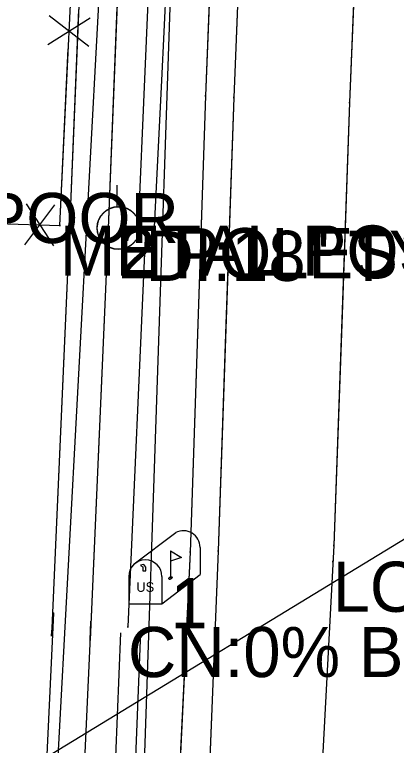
# Model space of a CAD drawing. Extents: x -99999 to 591807, y -99999 to 347168.
# Drawn here: x 591214 to 591252.1, y 320523.7 to 320596.6 of the extents above; entities that cross this region are included whole.
import ezdxf

# ---------------------------------------------------------------- set-up
doc = ezdxf.new("R2010")
doc.units = 0
for name, color, linetype in [('S_CURB', 7, 'Continuous'), ('S_DITCHLINE', 7, 'Continuous'), ('S_DRG_PT_SYM', 7, 'Continuous'), ('S_EDGE_PAVEMENT', 7, 'Continuous'), ('S_ELECTRIC_UTILITIES_ANNOT', 7, 'Continuous'), ('S_FENCE', 7, 'Continuous'), ('S_FENCE_ANNOT', 7, 'Continuous'), ('S_GAS_UTILITIES', 7, 'Continuous'), ('S_GRD_PT_SYM', 7, 'Continuous'), ('S_MAILBOX', 7, 'Continuous'), ('S_MAILBOX_ANNOT', 7, 'Continuous'), ('S_MSC_PT_SYM', 7, 'Continuous'), ('S_PAVEMENT_CROWN', 7, 'Continuous'), ('S_RDW_PT_SYM', 7, 'Continuous'), ('S_SHOULDER', 7, 'Continuous'), ('S_SIDE_DRAIN', 7, 'Continuous'), ('S_SIDE_DRAIN_ANNOT', 7, 'Continuous'), ('S_SIDEWALK', 7, 'Continuous'), ('S_UTILITY_POLE', 7, 'Continuous'), ('S_UTILITY_POLE_ANNOT', 7, 'Continuous'), ('S_UTL_PT_SYM', 7, 'Continuous'), ('S_WATER_UTILITIES', 7, 'Continuous')]:
    doc.layers.add(name, color=color, linetype=linetype)

msp = doc.modelspace()

# ---------------------------------------------------------------- linework, layer by layer
at = {"layer": 'S_CURB'}
msp.add_lwpolyline([(591407.501, 320558.912), (591363.862, 320560.823), (591322.937, 320562.802), (591286.066, 320564.459), (-99999, -99999)], dxfattribs=at)
at = {"layer": 'S_DITCHLINE'}
for points in [[(591226.335, 320575.526), (591226.979, 320590.136), (591227.623, 320604.745), (591228.267, 320619.355), (591228.911, 320633.965)], [(591227.95, 320575.425), (591228.667, 320589.998), (591229.385, 320604.572), (591230.103, 320619.146), (591230.821, 320633.72)], [(591223.986, 320468.51), (591224.633, 320485.141), (591225.28, 320501.773), (591225.927, 320518.405), (591226.574, 320535.036)], [(591222.009, 320468.936), (591222.651, 320485.44), (591223.293, 320501.945), (591223.935, 320518.45), (591224.577, 320534.954)]]:
    msp.add_lwpolyline(points, dxfattribs=at)
at = {"layer": 'S_DRG_PT_SYM'}
for points in [[(591227.047, 320575.022), (591227.047, 320575.072), (591227.047, 320575.022), (591226.997, 320575.022), (591227.047, 320575.022), (591227.047, 320574.972), (591227.047, 320575.022), (591227.097, 320575.022)], [(591225.295, 320535.531), (591225.295, 320535.582), (591225.295, 320535.531), (591225.245, 320535.531), (591225.295, 320535.531), (591225.295, 320535.481), (591225.295, 320535.531), (591225.345, 320535.531)]]:
    msp.add_lwpolyline(points, dxfattribs=at)
at = {"layer": 'S_EDGE_PAVEMENT'}
for points in [[(591157.816, 321374.558), (591171.996, 321326.2), (591184.501, 321283.667), (591196.965, 321241.411), (591212.283, 321187.826), (591223.284, 321148.219), (591233.116, 321106.873), (591242.974, 321050.292), (591247.278, 321006.148), (591248.487, 320958.254), (591248.173, 320914.304), (591247.117, 320868.716), (591245.559, 320824.189), (591244.165, 320785.581), (591242.251, 320742.557), (591240.726, 320705.613), (591238.924, 320663.696), (591237.267, 320623.329), (591235.848, 320588.307), (591234.304, 320543.116), (591232.694, 320503.413), (591231.224, 320460.428), (591229.562, 320424.545)], [(591236.557, 320605.818), (591235.848, 320588.307), (591235.076, 320565.712), (591234.304, 320543.116), (591233.499, 320523.265), (591232.694, 320503.413), (591231.959, 320481.921), (591231.224, 320460.428), (591230.393, 320442.487), (591229.562, 320424.545)]]:
    msp.add_lwpolyline(points, dxfattribs=at)
at = {"layer": 'S_FENCE'}
for p, q in [((591218.492, 320575.546), (591221.353, 320634.933)), ((591217.311, 320593.587), (591221.54, 320596.255)), ((591221.402, 320593.39), (591217.449, 320596.452)), ((591124.877, 320578.793), (591218.492, 320575.546)), ((591214.998, 320573.618), (591218.006, 320577.612)), ((591215.14, 320577.712), (591217.864, 320573.519))]:
    msp.add_line(p, q, dxfattribs=at)
msp.add_lwpolyline([(591218.492, 320575.546), (591219.341, 320593.16)], dxfattribs=at)
at = {"layer": 'S_GAS_UTILITIES'}
msp.add_line((591229.99, 320612.067), (591224.377, 320448.24), dxfattribs=at)
at = {"layer": 'S_GRD_PT_SYM'}
msp.add_lwpolyline([(591245.733, 320542.039), (591245.733, 320542.089), (591245.733, 320542.039), (591245.682, 320542.039), (591245.733, 320542.039), (591245.733, 320541.989), (591245.733, 320542.039), (591245.783, 320542.039)], close=True, dxfattribs=at)
at = {"layer": 'S_MAILBOX'}
for p, q in [((591225.926, 320541.824), (591230.06, 320544.933)), ((591229.541, 320543.113), (591229.541, 320540.398)), ((591232.492, 320543.459), (591232.492, 320540.744)), ((591225.372, 320540.55), (591225.372, 320537.835)), ((591228.696, 320537.835), (591232.492, 320540.744)), ((591228.696, 320540.55), (591228.696, 320537.835)), ((591225.372, 320537.835), (591228.696, 320537.835))]:
    msp.add_line(p, q, dxfattribs=at)
for points in [[(591229.541, 320543.113), (591230.649, 320542.448), (591229.541, 320542.102)], [(591226.556, 320541.665), (591226.778, 320541.527), (591226.778, 320541.139), (591227.083, 320541.139), (591227.083, 320541.499), (591226.889, 320541.748), (591226.556, 320541.693)]]:
    msp.add_lwpolyline(points, dxfattribs=at)
for centre, end in [((591230.83, 320543.459), 117.57184), ((591227.034, 320540.55), 180)]:
    msp.add_arc(centre, 1.662, 0, end, dxfattribs=at)
msp.add_ellipse((591229.541, 320540.398), major_axis=(0.145, 0.132), ratio=0.564646, dxfattribs=at)
at = {"layer": 'S_MSC_PT_SYM'}
for points in [[(591219.52, 320576.847), (591219.57, 320576.845), (591219.52, 320576.847), (591219.522, 320576.897), (591219.52, 320576.847), (591219.47, 320576.85), (591219.52, 320576.847), (591219.517, 320576.797)], [(591223.33, 320575.279), (591223.38, 320575.277), (591223.33, 320575.279), (591223.332, 320575.329), (591223.33, 320575.279), (591223.28, 320575.281), (591223.33, 320575.279), (591223.328, 320575.229)], [(591217.863, 320536.898), (591217.913, 320536.895), (591217.863, 320536.898), (591217.866, 320536.948), (591217.863, 320536.898), (591217.814, 320536.9), (591217.863, 320536.898), (591217.861, 320536.848)], [(591221.586, 320536.045), (591221.636, 320536.042), (591221.586, 320536.045), (591221.588, 320536.094), (591221.586, 320536.045), (591221.536, 320536.047), (591221.586, 320536.045), (591221.584, 320535.995)], [(591217.679, 320534.666), (591217.629, 320534.671), (591217.679, 320534.666), (591217.674, 320534.617), (591217.679, 320534.666), (591217.728, 320534.662), (591217.679, 320534.666), (591217.683, 320534.716)], [(591221.529, 320534.239), (591221.479, 320534.241), (591221.529, 320534.239), (591221.527, 320534.189), (591221.529, 320534.239), (591221.579, 320534.238), (591221.529, 320534.239), (591221.53, 320534.289)]]:
    msp.add_lwpolyline(points, close=True, dxfattribs=at)
msp.add_lwpolyline([(591218.492, 320575.546), (591218.492, 320575.596), (591218.492, 320575.546), (591218.442, 320575.546), (591218.492, 320575.546), (591218.492, 320575.496), (591218.492, 320575.546), (591218.542, 320575.546)], dxfattribs=at)
at = {"layer": 'S_PAVEMENT_CROWN'}
for points in [[(591169.393, 321376.166), (591182.702, 321330.303), (591196.053, 321285.507), (591208.234, 321244.204), (591224.138, 321189.501), (591234.43, 321151.835), (591245.74, 321106.049), (591255.457, 321050.575), (591259.103, 321006.376), (591260.258, 320958.142), (591259.827, 320913.406), (591258.406, 320868.937), (591257.042, 320823.073), (591255.423, 320785.261), (591253.776, 320741.805), (591252.116, 320704.89), (591250.293, 320661.391), (591248.847, 320623.224), (591247.409, 320587.797), (591245.838, 320543.645), (591243.645, 320502.375), (591242.309, 320460.161), (591240.802, 320424.401)], [(591248.128, 320605.51), (591247.409, 320587.797), (591246.623, 320565.721), (591245.838, 320543.645), (591244.741, 320523.01), (591243.645, 320502.375), (591242.977, 320481.268), (591242.309, 320460.161), (591241.556, 320442.281), (591240.802, 320424.401)]]:
    msp.add_lwpolyline(points, dxfattribs=at)
at = {"layer": 'S_RDW_PT_SYM'}
for points in [[(591233.024, 320588.472), (591233.074, 320588.471), (591233.024, 320588.472), (591233.025, 320588.522), (591233.024, 320588.472), (591232.974, 320588.474), (591233.024, 320588.472), (591233.022, 320588.422)], [(591235.848, 320588.307), (591235.898, 320588.305), (591235.848, 320588.307), (591235.85, 320588.357), (591235.848, 320588.307), (591235.798, 320588.309), (591235.848, 320588.307), (591235.846, 320588.257)], [(591247.409, 320587.797), (591247.459, 320587.795), (591247.409, 320587.797), (591247.41, 320587.847), (591247.409, 320587.797), (591247.359, 320587.799), (591247.409, 320587.797), (591247.407, 320587.747)], [(591234.304, 320543.116), (591234.354, 320543.114), (591234.304, 320543.116), (591234.306, 320543.166), (591234.304, 320543.116), (591234.254, 320543.118), (591234.304, 320543.116), (591234.302, 320543.066)], [(591245.838, 320543.645), (591245.887, 320543.642), (591245.838, 320543.645), (591245.84, 320543.695), (591245.838, 320543.645), (591245.788, 320543.648), (591245.838, 320543.645), (591245.835, 320543.595)], [(591231.51, 320542.985), (591231.559, 320542.983), (591231.51, 320542.985), (591231.512, 320543.035), (591231.51, 320542.985), (591231.46, 320542.987), (591231.51, 320542.985), (591231.507, 320542.935)]]:
    msp.add_lwpolyline(points, close=True, dxfattribs=at)
at = {"layer": 'S_SHOULDER'}
for points in [[(591245.875, 320932.116), (591246.336, 320914.379), (591244.03, 320869.095), (591242.236, 320824.086), (591240.926, 320786.072), (591238.956, 320744.968), (591237.561, 320705.47), (591236.035, 320663.813), (591234.455, 320624.274), (591233.024, 320588.472), (591231.51, 320542.985), (591229.6, 320503.548), (591227.673, 320460.661), (591225.848, 320425.042)], [(591233.739, 320606.373), (591233.024, 320588.472), (591232.267, 320565.729), (591231.51, 320542.985), (591230.555, 320523.267), (591229.6, 320503.548), (591228.637, 320482.105), (591227.673, 320460.661), (591226.761, 320442.852), (591225.848, 320425.042)]]:
    msp.add_lwpolyline(points, dxfattribs=at)
at = {"layer": 'S_SIDE_DRAIN'}
msp.add_line((591227.047, 320575.022), (591225.295, 320535.531), dxfattribs=at)
at = {"layer": 'S_SIDEWALK'}
for points in [[(591219.908, 320876.067), (591231.73, 320875.493), (591230.676, 320851.856), (591229.672, 320820.621), (591229.014, 320806.939), (591228.338, 320790.518), (591228.051, 320787.963), (591226.647, 320756.32), (591225.614, 320729.855), (591224.094, 320691.665), (591222.325, 320649.311), (591221.216, 320617.3), (591219.52, 320576.847), (591217.679, 320534.666), (591217.863, 320536.898), (591216.224, 320501.633), (591214.624, 320467.913), (591200.757, 320468.742)], [(591225.013, 320617.584), (591223.33, 320575.279), (591221.529, 320534.239), (591221.586, 320536.045), (591219.997, 320501.136), (591218.495, 320468.181), (591225.523, 320467.907), (591225.412, 320464.068), (591218.297, 320464.183), (591216.954, 320432.825)], [(591225.013, 320617.584), (591224.171, 320596.432), (591223.33, 320575.279), (591222.429, 320554.759), (591221.529, 320534.239), (591221.586, 320536.045), (591220.791, 320518.59), (591219.997, 320501.136), (591219.246, 320484.658), (591218.495, 320468.181), (591225.523, 320467.907), (591225.412, 320464.068), (591218.297, 320464.183), (591217.625, 320448.504), (591216.954, 320432.825)], [(591220.368, 320597.074), (591219.52, 320576.847), (591218.599, 320555.757), (591217.679, 320534.666), (591217.863, 320536.898), (591217.044, 320519.265), (591216.224, 320501.633), (591215.424, 320484.773), (591214.624, 320467.913), (591200.757, 320468.742)]]:
    msp.add_lwpolyline(points, dxfattribs=at)
at = {"layer": 'S_UTILITY_POLE'}
for p, q in [((591224.239, 320577.451), (591224.239, 320579.559)), ((591224.239, 320577.425), (591224.239, 320579.533))]:
    msp.add_line(p, q, dxfattribs=at)
for centre in [(591224.361, 320575.309), (591224.362, 320575.284)]:
    msp.add_circle(centre, 2.127, dxfattribs=at)
at = {"layer": 'S_UTL_PT_SYM'}
msp.add_lwpolyline([(591245.733, 320542.039), (591245.733, 320542.089), (591245.733, 320542.039), (591245.682, 320542.039), (591245.733, 320542.039), (591245.733, 320541.989), (591245.733, 320542.039), (591245.783, 320542.039)], dxfattribs=at)
at = {"layer": 'S_WATER_UTILITIES'}
msp.add_line((591223.46, 320618.063), (591214.304, 320448.446), dxfattribs=at)

# ---------------------------------------------------------------- texts
at = {"layer": 'S_ELECTRIC_UTILITIES_ANNOT'}
msp.add_text('LOWEST UTILITY LINE', height=5, dxfattribs=at).set_placement((591245.733, 320537.039))
at = {"layer": 'S_FENCE_ANNOT'}
for p in [(591124.877, 320573.793), (591218.492, 320570.546)]:
    msp.add_text('METAL POST WEBED NET,POOR', height=5, dxfattribs=at).set_placement(p)
at = {"layer": 'S_MAILBOX'}
msp.add_text('US', height=0.96, rotation=360, dxfattribs=at).set_placement((591226.136, 320539.029))
at = {"layer": 'S_MAILBOX_ANNOT'}
msp.add_text('1', height=5, dxfattribs=at).set_placement((591229.541, 320535.398))
at = {"layer": 'S_SIDE_DRAIN_ANNOT'}
for s, p in [('DI:18" TY:CMP CN:20% BTTM OF PI', (591227.047, 320570.022)), ('CN:0% BTTM OF PIPE', (591225.295, 320530.531))]:
    msp.add_text(s, height=5, dxfattribs=at).set_placement(p)
at = {"layer": 'S_UTILITY_POLE_ANNOT'}
msp.add_text('2 POLES', height=5, dxfattribs=at).set_placement((591224.362, 320570.284))

doc.saveas('drawing.dxf')
